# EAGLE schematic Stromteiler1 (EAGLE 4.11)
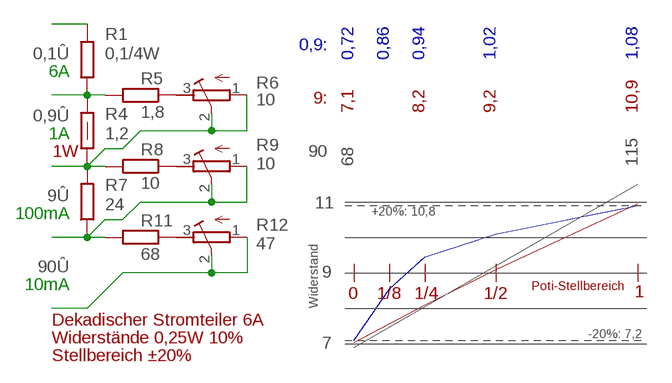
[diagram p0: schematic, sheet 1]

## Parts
R1  0,1/4W  R0603  [0603]
R4  1,2  R0603  [0603]
R5  1,8  R0603  [0603]
R6  10  RP-ACP6L  [CA6V]
R7  24  R0603  [0603]
R8  10  R0603  [0603]
R9  10  RP-ACP6L  [CA6V]
R11  68  R0603  [0603]
R12  47  RP-ACP6L  [CA6V]

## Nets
N$1: R5.1 R6.3
N$2: R4.1 R6.1 R6.2 R7.2 R8.2
N$3: R8.1 R9.3
N$4: R11.1 R12.3
N$5: R1.2
N$6: R1.1 R4.2 R5.2
N$8: R7.1 R9.1 R9.2 R11.2
N$9: R12.1 R12.2

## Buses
B$1

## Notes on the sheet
- 0,9:
- 0,1Û | 0,72 | 0,86 | 0,94 | 1,02 | 1,08
- 6A
- 9:
- 7,1 | 8,2 | 9,2 | 10,9
- 0,9Û
- 1A
- 1W | 90
- 68 | 115
- 9Û
- 11
- 100mA | +20%: 10,8
- 90Û
- 9
- 10mA | Poti-Stellbereich
- 0 | 1/8 | 1/4 | 1/2 | 1
- Widerstand
- Dekadischer Stromteiler 6A
- -20%: 7,2
- Widerstände 0,25W 10%
- 7
- Stellbereich ±20%

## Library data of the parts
R1 R4 R5 R7 R8 R11 = TPS63060:R: Widerstand
R6 R9 R12 = TPS63060:RP: Einstellwiderstand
